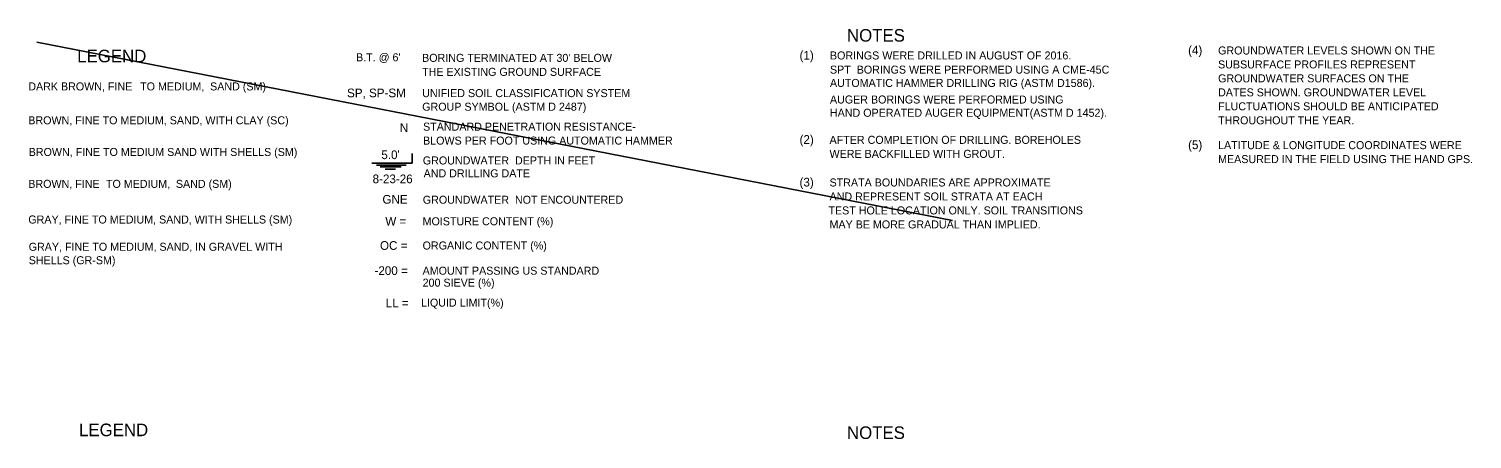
# Model space of a CAD drawing. Extents: x 0 to 331, y -72 to 117.
# Drawn here: x 28.65 to 53.9, y -23.39 to -16.21 of the extents above; entities that cross this region are included whole.
import ezdxf

# ---------------------------------------------------------------- set-up
doc = ezdxf.new("R2010")
doc.units = 0
doc.layers.add('1-BORE', color=7, linetype='Continuous')
doc.layers.add('1-TEXT', color=7, linetype='Continuous')

msp = doc.modelspace()

# ---------------------------------------------------------------- linework, layer by layer
at = {"layer": '1-BORE'}
msp.add_line((28.787, -16.441), (44.813, -19.563), dxfattribs=at)
at = {"layer": '1-TEXT'}
for p, q in [((35.355, -18.558), (35.355, -18.389)), ((34.651, -18.558), (35.355, -18.558)), ((34.732, -18.594), (35.251, -18.594)), ((34.796, -18.627), (35.165, -18.627)), ((34.883, -18.663), (35.063, -18.663))]:
    msp.add_line(p, q, dxfattribs=at)

# ---------------------------------------------------------------- texts
for s, height, p in [('NOTES', 0.22, (42.964, -16.433)), ('LEGEND', 0.22, (29.494, -16.795)), ("B.T. @ 6'", 0.14, (34.374, -16.777)), ("BORING TERMINATED AT 30' BELOW", 0.14, (35.529, -16.787)), ('(1)', 0.1521, (42.134, -16.748)), ('BORINGS WERE DRILLED IN AUGUST OF 2016.', 0.14, (42.666, -16.745)), ('(4)', 0.1521, (48.933, -16.658)), ('GROUNDWATER LEVELS SHOWN ON THE ', 0.14, (49.458, -16.658)), ('THE EXISTING GROUND SURFACE', 0.14, (35.529, -17.032)), ('SPT  BORINGS WERE PERFORMED USING A CME-45C', 0.14, (42.666, -16.993)), ('SUBSURFACE PROFILES REPRESENT', 0.14, (49.458, -16.902)), ('DARK BROWN, FINE ', 0.14, (28.638, -17.287)), ('TO MEDIUM, ', 0.14, (30.595, -17.287)), ('SAND (SM)', 0.14, (31.819, -17.287)), ('AUTOMATIC HAMMER DRILLING RIG (ASTM D1586).', 0.14, (42.666, -17.226)), ('GROUNDWATER SURFACES ON THE', 0.14, (49.458, -17.146)), ('SP, SP-SM ', 0.1521, (34.216, -17.407)), ('UNIFIED SOIL CLASSIFICATION SYSTEM', 0.14, (35.531, -17.404)), ('AUGER BORINGS WERE PERFORMED USING', 0.14, (42.666, -17.516)), ('DATES SHOWN. GROUNDWATER LEVEL', 0.14, (49.458, -17.391)), ('GROUP SYMBOL (ASTM D 2487)', 0.14, (35.531, -17.642)), ('HAND OPERATED AUGER EQUIPMENT(ASTM D 1452).', 0.14, (42.666, -17.748)), ('FLUCTUATIONS SHOULD BE ANTICIPATED ', 0.14, (49.458, -17.635)), ('BROWN, FINE TO MEDIUM, SAND, WITH CLAY (SC)', 0.14, (28.638, -17.88)), ('N', 0.152, (35.139, -18.016)), ('STANDARD PENETRATION RESISTANCE-', 0.14, (35.546, -17.991)), ('THROUGHOUT THE YEAR.', 0.14, (49.458, -17.88)), ('BLOWS PER FOOT USING AUTOMATIC HAMMER', 0.14, (35.546, -18.235)), ('(2)', 0.1521, (42.134, -18.222)), ('AFTER COMPLETION OF DRILLING. BOREHOLES', 0.14, (42.659, -18.222)), ('(5)', 0.1521, (48.933, -18.315)), ('LATITUDE & LONGITUDE COORDINATES WERE ', 0.14, (49.458, -18.315)), ('BROWN, FINE TO MEDIUM SAND WITH SHELLS (SM)', 0.14, (28.645, -18.434)), ("  5.0'", 0.1521, (34.703, -18.489)), ('WERE BACKFILLED WITH GROUT.', 0.14, (42.659, -18.467)), ('MEASURED IN THE FIELD USING THE HAND GPS.', 0.14, (49.458, -18.559)), ('GROUNDWATER  DEPTH IN FEET', 0.14, (35.542, -18.583)), ('AND DRILLING DATE', 0.14, (35.556, -18.808)), ('BROWN, FINE ', 0.14, (28.638, -18.992)), ('TO MEDIUM, ', 0.14, (29.997, -18.992)), ('SAND (SM)', 0.14, (31.221, -18.992)), ('8-23-26', 0.1521, (34.663, -18.911)), ('(3)', 0.1521, (42.134, -18.968)), ('STRATA BOUNDARIES ARE APPROXIMATE', 0.14, (42.659, -18.968)), ('GNE', 0.1521, (34.835, -19.269)), ('GROUNDWATER  NOT ENCOUNTERED ', 0.14, (35.542, -19.27)), ('AND REPRESENT SOIL STRATA AT EACH', 0.14, (42.659, -19.213)), ('TEST HOLE LOCATION ONLY. SOIL TRANSITIONS', 0.14, (42.64, -19.457)), ('GRAY, FINE TO MEDIUM, SAND, WITH SHELLS (SM)', 0.14, (28.638, -19.616)), ('W =', 0.1521, (34.886, -19.653)), ('MOISTURE CONTENT (%)', 0.14, (35.538, -19.647)), ('MAY BE MORE GRADUAL THAN IMPLIED.', 0.14, (42.659, -19.702)), ('GRAY, FINE TO MEDIUM, SAND, IN GRAVEL WITH', 0.14, (28.645, -20.093)), ('OC =', 0.1521, (34.792, -20.077)), ('ORGANIC CONTENT (%)', 0.14, (35.538, -20.071)), ('SHELLS (GR-SM)', 0.14, (28.645, -20.329)), ('-200 =', 0.1521, (34.696, -20.517)), ('AMOUNT PASSING US STANDARD', 0.14, (35.538, -20.512)), ('200 SIEVE (%)', 0.14, (35.538, -20.721)), ('LL =', 0.1521, (34.893, -21.083)), (' LIQUID LIMIT(%%%)', 0.14, (35.458, -21.071)), ('LEGEND', 0.22, (29.526, -23.338)), ('NOTES', 0.22, (42.964, -23.387))]:
    msp.add_text(s, height=height, dxfattribs=at).set_placement(p)

doc.saveas('drawing.dxf')
